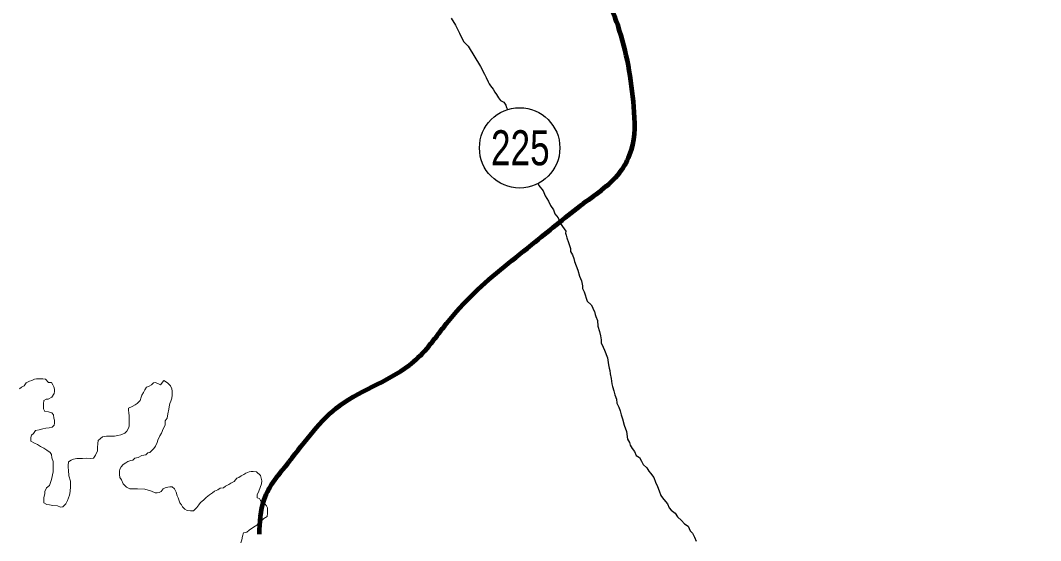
# Model space of a CAD drawing. Extents: x 553962 to 842807, y 8883888 to 9032388.
# Drawn here: x 628002 to 638188, y 8939733 to 8944931 of the extents above; entities that cross this region are included whole.
import ezdxf
from ezdxf.enums import TextEntityAlignment as Align

# ---------------------------------------------------------------- set-up
doc = ezdxf.new("R2010")
doc.units = 0
doc.header["$LTSCALE"] = 20
for name, color, linetype, lineweight in [('12', 7, 'Continuous', 25), ('25', 7, 'Continuous', 13), ('48', 7, 'Continuous', 25), ('9', 7, 'Continuous', 90)]:
    doc.layers.add(name, color=color, linetype=linetype, lineweight=lineweight)

msp = doc.modelspace()

# ---------------------------------------------------------------- linework, layer by layer
at = {"layer": '12'}
for points in [[(632303.17, 8944952.49), (632347.65, 8944882.1), (632387.06, 8944801.73), (632426.45, 8944718.85), (632471.12, 8944673.49), (632594.63, 8944469.89)], [(632594.63, 8944469.89), (632634.05, 8944392.01), (632653.81, 8944359.33), (632673.5, 8944316.65), (632680.85, 8944296.57), (632695.7, 8944276.45), (632720.46, 8944243.74), (632737.74, 8944213.58), (632755.07, 8944190.93), (632774.84, 8944158.25), (632794.63, 8944130.59), (632827.01, 8944112.85), (632849.29, 8944082.65), (632856.62, 8944060.08), (632865.38, 8944039.96)], [(633172.25, 8943297.09), (633178.35, 8943281.85), (633220.46, 8943229), (633240.09, 8943178.8), (633274.69, 8943123.49), (633294.37, 8943080.8), (633324.06, 8943038.05), (633338.76, 8942997.89), (633370.97, 8942957.63), (633390.58, 8942904.92), (633430.17, 8942849.58), (633447.49, 8942824.43), (633444.83, 8942804.42), (633452.19, 8942784.34), (633456.98, 8942756.78), (633474.14, 8942711.6), (633483.92, 8942681.49), (633493.69, 8942651.38), (633493.46, 8942621.34), (633513.22, 8942588.66), (633527.94, 8942551.01), (633532.72, 8942520.94), (633549.9, 8942478.26), (633567.08, 8942435.59), (633584.13, 8942375.39), (633603.8, 8942330.2), (633613.42, 8942280.07), (633613.21, 8942252.53), (633630.45, 8942217.37), (633659.78, 8942127.05)], [(633659.78, 8942127.05), (633702.01, 8942089.21), (633714.34, 8942066.6), (633721.69, 8942046.52), (633734.01, 8942021.4), (633741.28, 8941991.32), (633748.63, 8941971.24), (633763.35, 8941933.59), (633767.92, 8941875.98), (633785, 8941820.79), (633792.19, 8941778.18), (633799.38, 8941738.07), (633799.17, 8941710.53), (633818.84, 8941665.35), (633833.62, 8941635.2), (633863.05, 8941559.9)], [(633863.05, 8941559.9), (633872.53, 8941489.74), (633879.76, 8941454.64), (633887.09, 8941432.07), (633891.85, 8941399.49), (633899.01, 8941354.37), (633906.09, 8941299.25), (633913.39, 8941271.66), (633928.07, 8941229.01), (633935.26, 8941188.9), (633952.45, 8941146.23), (633957.14, 8941106.14), (633976.85, 8941065.95), (633991.57, 8941028.3), (633998.77, 8940988.2), (634013.49, 8940950.55), (634030.5, 8940885.35), (634055.03, 8940822.59)], [(634055.03, 8940822.59), (634064.46, 8940747.42), (634084.23, 8940714.75), (634091.52, 8940687.16), (634111.26, 8940651.98), (634133.54, 8940621.79), (634150.76, 8940584.12), (634183.12, 8940563.88), (634202.84, 8940526.2), (634220.1, 8940493.54), (634257.37, 8940460.74), (634277.13, 8940428.07), (634291.96, 8940405.44), (634326.65, 8940362.65), (634343.82, 8940317.48), (634363.48, 8940272.28), (634380.67, 8940229.61), (634395.33, 8940184.44), (634412.64, 8940159.3), (634442.39, 8940124.05), (634462.23, 8940101.39), (634479.43, 8940061.21), (634499.27, 8940038.55), (634539.03, 8940005.74), (634563.78, 8939970.53), (634601.02, 8939935.23), (634633.27, 8939899.98), (634670.61, 8939877.19), (634690.28, 8939832), (634712.6, 8939806.82), (634732.32, 8939769.13), (634749.5, 8939726.46)]]:
    msp.add_lwpolyline(points, dxfattribs=at)
at = {"layer": '25'}
for points in [[(628231.92, 8941078.93), (628232.07, 8941098.96), (628234.82, 8941131.48), (628257.44, 8941146.35), (628277.45, 8941146.22), (628315.12, 8941166), (628340.41, 8941203.39), (628340.56, 8941223.41), (628340.74, 8941245.94), (628335.92, 8941271.01), (628326.07, 8941291.1), (628311.22, 8941311.23), (628283.73, 8941313.92), (628251.46, 8941346.67), (628223.97, 8941349.36), (628193.96, 8941349.56), (628163.95, 8941349.76), (628143.9, 8941344.89), (628116.29, 8941332.55), (628093.75, 8941327.69), (628058.6, 8941310.4), (628038.37, 8941280.49), (628013.24, 8941265.64), (627993.1, 8941248.24)], [(629399.03, 8941289.01), (629351.7, 8941314.36), (629331.65, 8941309.49), (629311.5, 8941289.59), (629286.39, 8941277.24), (629261.29, 8941264.89), (629243.59, 8941239.97), (629230.88, 8941212.52), (629215.68, 8941187.58), (629208, 8941165.1), (629197.75, 8941132.62), (629167.51, 8941102.78), (629147.41, 8941090.39), (629117.26, 8941073.07), (629082.12, 8941055.78), (629081.96, 8941035.75), (629084.25, 8941008.2), (629089.05, 8940980.63), (629088.82, 8940950.59), (629088.55, 8940915.53), (629088.27, 8940877.98), (629080.59, 8940855.51), (629065.36, 8940825.57), (629045.22, 8940808.17), (629005.07, 8940790.91), (628975, 8940783.6), (628939.93, 8940776.32), (628917.42, 8940776.48), (628882.41, 8940776.71), (628859.9, 8940776.85), (628822.33, 8940769.59), (628802.21, 8940754.7), (628779.52, 8940732.32), (628774.29, 8940702.32), (628771.51, 8940664.78), (628771.24, 8940629.73), (628750.91, 8940587.3), (628730.67, 8940557.4), (628698.14, 8940555.11), (628665.63, 8940555.32), (628623.09, 8940553.1), (628600.58, 8940553.25), (628565.57, 8940553.48), (628530.5, 8940546.21), (628507.91, 8940536.34), (628480.27, 8940519), (628477.5, 8940483.97), (628477.35, 8940463.94), (628482.14, 8940436.37), (628484.21, 8940378.78), (628501.33, 8940328.59), (628500.91, 8940273.51), (628498.03, 8940223.46), (628490.24, 8940185.96), (628472.34, 8940133.51), (628454.58, 8940101.08), (628424.34, 8940071.24), (628401.79, 8940066.38), (628371.89, 8940081.6), (628324.39, 8940084.41), (628291.92, 8940089.64), (628264.45, 8940094.83), (628237.05, 8940110.03), (628234.72, 8940132.58), (628234.97, 8940165.12), (628245.24, 8940200.1), (628245.41, 8940222.63), (628263.2, 8940260.07), (628293.4, 8940284.9), (628311.35, 8940342.37), (628329.45, 8940419.85), (628329.95, 8940484.94), (628327.74, 8940525.01), (628315.51, 8940560.14), (628313.26, 8940592.71), (628298.4, 8940612.83), (628266.06, 8940635.58), (628236.2, 8940655.8), (628201.32, 8940673.56), (628173.96, 8940693.77), (628141.54, 8940706.5), (628106.69, 8940726.76), (628104.47, 8940764.33), (628112.14, 8940786.81), (628132.29, 8940804.2), (628152.52, 8940834.1), (628187.59, 8940841.39), (628225.18, 8940851.15), (628255.23, 8940855.96), (628287.78, 8940860.75), (628317.85, 8940868.07), (628337.99, 8940885.46), (628340.67, 8940907.97), (628340.89, 8940938.01), (628336.04, 8940958.07), (628331.27, 8940988.15), (628313.94, 8941010.79), (628281.5, 8941021.01), (628246.51, 8941023.75), (628231.69, 8941048.89), (628231.92, 8941078.93)], [(630397.58, 8940383.64), (630357.83, 8940418.95), (630325.36, 8940424.17), (630305.35, 8940424.3), (630285.31, 8940419.43), (630252.7, 8940407.13), (630232.6, 8940394.74), (630204.97, 8940379.91), (630182.33, 8940362.53), (630162.28, 8940357.66), (630134.52, 8940325.3), (630101.88, 8940307.99), (630081.76, 8940293.1), (630049.11, 8940275.79), (630028.99, 8940260.9), (629996.44, 8940256.11), (629973.81, 8940241.24), (629938.69, 8940226.45), (629918.55, 8940209.06), (629888.4, 8940191.73), (629855.68, 8940164.41), (629830.46, 8940137.04), (629800.28, 8940114.71), (629782.58, 8940089.79), (629764.86, 8940062.37), (629729.6, 8940030.05), (629699.59, 8940030.25), (629667.11, 8940035.48), (629642.2, 8940048.16), (629619.86, 8940070.84), (629610.01, 8940090.93), (629595.16, 8940111.06), (629587.8, 8940131.13), (629575.53, 8940161.26), (629568.18, 8940181.33), (629555.94, 8940216.46), (629538.7, 8940251.63), (629516.33, 8940269.3), (629493.82, 8940269.45), (629473.79, 8940267.08), (629448.72, 8940259.73), (629426.14, 8940249.87), (629408.44, 8940224.95), (629385.84, 8940212.58), (629365.81, 8940210.21), (629345.8, 8940210.35), (629310.92, 8940228.1), (629243.55, 8940248.57), (629171.02, 8940249.05), (629128.51, 8940249.33), (629093.51, 8940252.07), (629061.11, 8940267.3), (629028.85, 8940300.07), (629011.64, 8940340.24), (628994.31, 8940362.88), (628992.04, 8940392.94), (628992.28, 8940425.48), (628994.94, 8940445.49), (629007.63, 8940470.44), (629027.81, 8940492.84), (629052.95, 8940510.2), (629073.06, 8940522.58), (629105.64, 8940532.39), (629125.69, 8940537.26), (629145.86, 8940557.15), (629178.42, 8940564.45), (629213.59, 8940584.24), (629253.66, 8940591.49), (629273.82, 8940611.39), (629293.85, 8940613.75), (629314.01, 8940633.65), (629334.17, 8940653.55), (629351.85, 8940675.96), (629367.14, 8940713.41), (629372.31, 8940735.91), (629392.64, 8940778.33), (629410.36, 8940805.76), (629428.21, 8940850.7), (629446, 8940888.14), (629446.3, 8940928.19), (629466.52, 8940955.6), (629474.35, 8940998.11), (629482.21, 8941045.62), (629487.39, 8941068.12), (629492.66, 8941103.13), (629505.33, 8941125.58), (629513.06, 8941155.57), (629518.29, 8941185.58), (629518.6, 8941225.63), (629513.77, 8941248.2), (629498.99, 8941278.34), (629471.71, 8941308.56), (629434.37, 8941331.34), (629399.03, 8941289.01)], [(630202.39, 8939711.48), (630212.62, 8939741.46), (630220.39, 8939776.45), (630228.16, 8939811.45), (630263.21, 8939816.23), (630285.87, 8939836.1), (630328.62, 8939865.87), (630361.3, 8939888.18), (630399.06, 8939920.48), (630431.82, 8939952.81), (630464.51, 8939975.12), (630469.76, 8940007.63), (630470, 8940040.18), (630467.66, 8940060.22), (630460.3, 8940080.3), (630442.95, 8940100.44), (630420.55, 8940115.61), (630398.18, 8940133.28), (630388.33, 8940153.38), (630365.88, 8940161.03), (630366.11, 8940191.08), (630383.9, 8940228.51), (630396.67, 8940263.48), (630409.46, 8940300.94), (630412.19, 8940330.97), (630397.58, 8940383.64)]]:
    msp.add_lwpolyline(points, dxfattribs=at)
at = {"layer": '48'}
msp.add_circle((632986.55, 8943656.42), 401.28, dxfattribs=at)
at = {"layer": '9'}
for points in [[(637260.63, 8972975.84), (641524.45, 8971056.24), (652526.05, 8965412.73), (653164.33, 8965062.83), (670790.48, 8953770.1), (686194.04, 8943929.95), (696283.29, 8937647.07)], [(630387.41, 8939797.8), (630434.25, 8940142.1), (630686.47, 8940523.63), (631192.1, 8941084.18), (631927.52, 8941519.78), (632256.08, 8941901.85), (632534.19, 8942207.62), (633141.92, 8942718.26), (633623.16, 8943101.43), (634002.92, 8943433.23), (634103.5, 8943636.48), (634126.4, 8944067.02), (633968.91, 8944876.03), (633685.24, 8945506.93), (633295.28, 8946896.57), (633418.31, 8947606.31), (633184.94, 8948338.83), (632825.23, 8948918.56), (632848.42, 8949298.47), (633991.44, 8949661.01), (634446.78, 8950119.94), (634848.23, 8951084.81), (634971.26, 8951794.54), (634968.71, 8952224.91), (635094.29, 8952504.28), (635191.88, 8953213.83), (635441.4, 8954051.05), (635362.8, 8954430.24), (634875.26, 8955110.32)]]:
    msp.add_spline(points, degree=3, dxfattribs=at)

# ---------------------------------------------------------------- texts
at = {"layer": '48', "width": 0.75}
msp.add_text('225', height=350, dxfattribs=at).set_placement((632993.2, 8943483.08), align=Align.CENTER)

doc.saveas('drawing.dxf')
